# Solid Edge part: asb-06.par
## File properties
Author: nakano
Template: iso metric part.par
Last saved by: nakano
Revision: 4
Application: Solid Edge
Density: 2915.08921255936 kg/m^3
Accuracy: 0.990
Username: nakano
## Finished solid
Body 1: solid body, 20 faces, 44 edges, 16 vertices.
  Faces by surface: cylinder 14, plane 6
  Edges by curve: circle 28, line 16
Bounding box of the edges (mm): 34.925 x 27.610 x 24.587, from (-34.925, 0, -12.2936) to (0, 27.6098, 12.2936).
Cylindrical faces by radius (mm): R0.254 x1, R1.1938 x8, R2.54 x1, R4.0005 x2, R12.2936 x2
Planar faces by outward normal: +x 1, +y 1, +z 1, -x 1, -y 1, -z 1
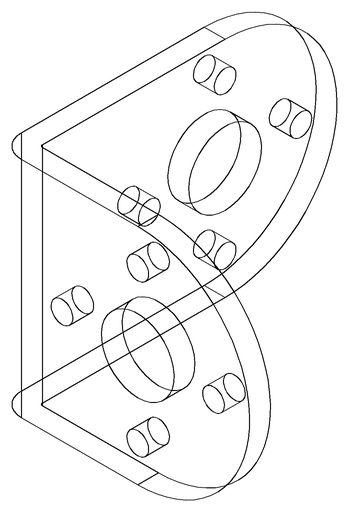
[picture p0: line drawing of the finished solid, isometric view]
